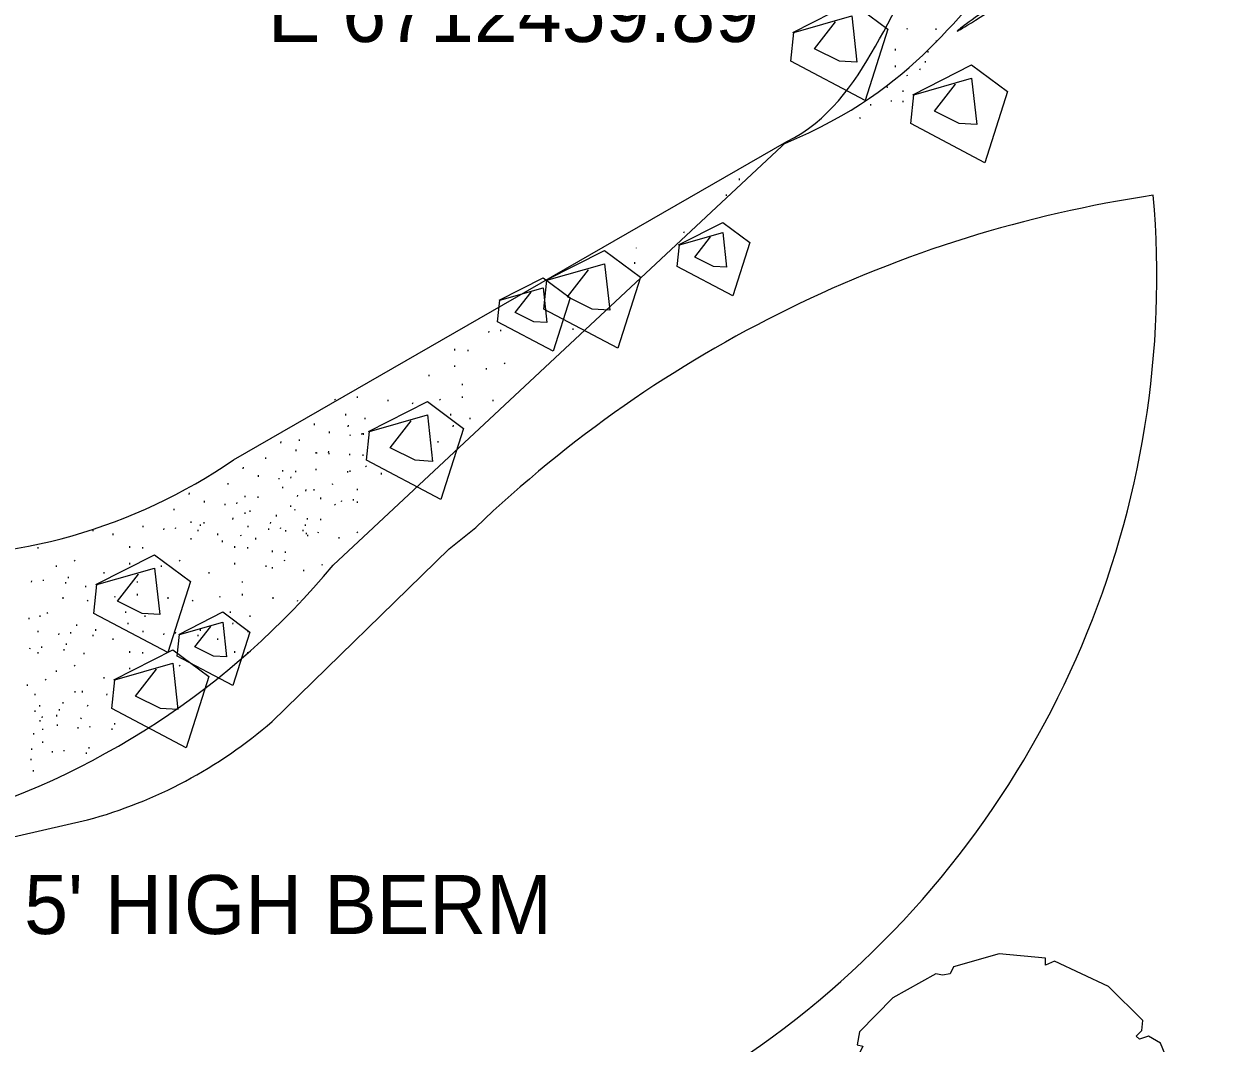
# Model space of a CAD drawing. Extents: x 6712138 to 6712574, y 1869536 to 1870160.
# Drawn here: x 6712397.9 to 6712471.1, y 1869628.8 to 1869691 of the extents above; entities that cross this region are included whole.
import ezdxf

# ---------------------------------------------------------------- set-up
doc = ezdxf.new("R2010")
doc.units = 0
for name, color, linetype in [('A-COLS', 7, 'Continuous'), ('A-FLOR-PATT', 7, 'Continuous'), ('A-WALL', 7, 'Continuous'), ('I-WALL', 7, 'Continuous'), ('L-SITE-PAVE', 7, 'Continuous'), ('L-tree', 7, 'Continuous'), ('P-SANR-FIXT', 7, 'Continuous')]:
    doc.layers.add(name, color=color, linetype=linetype)

# ---------------------------------------------------------------- blocks, each defined once
blk = doc.blocks.new('TREE 1')
at = {"layer": 'L-tree'}
for p, q in [((-0.0275, 0.572), (-0.1682, 0.5324)), ((0.1167, 0.5588), (-0.0275, 0.572)), ((0.1167, 0.5368), (0.1167, 0.5588)), ((-0.1682, 0.5324), (-0.1785, 0.5104)), ((0.1441, 0.55), (0.1167, 0.5368)), ((0.3123, 0.4708), (0.1441, 0.55)), ((-0.2231, 0.5104), (-0.357, 0.4356)), ((-0.2025, 0.506), (-0.2231, 0.5104)), ((-0.1785, 0.5104), (-0.2025, 0.506)), ((0.4187, 0.3652), (0.3123, 0.4708)), ((-0.357, 0.4356), (-0.4599, 0.33)), ((0.4153, 0.3344), (0.4187, 0.3652)), ((-0.4599, 0.33), (-0.4668, 0.2904)), ((0.3981, 0.3168), (0.4153, 0.3344)), ((0.4084, 0.308), (0.3981, 0.3168)), ((0.4359, 0.3168), (0.4084, 0.308)), ((0.4737, 0.2948), (0.4359, 0.3168)), ((-0.4599, 0.264), (-0.4908, 0.2596)), ((-0.4668, 0.2904), (-0.4496, 0.286)), ((-0.4496, 0.286), (-0.4599, 0.264)), ((0.5183, 0.1848), (0.4737, 0.2948)), ((-0.4908, 0.2596), (-0.5389, 0.2156)), ((-0.5389, 0.2156), (-0.5766, 0.0528)), ((0.5183, 0.1496), (0.5183, 0.1848)), ((0.5423, 0.1012), (0.5183, 0.1496)), ((0.5492, -0.0308), (0.5423, 0.1012)), ((-0.5766, 0.0528), (-0.5595, -0.1232)), ((-0.0034, 0.0176), (-0.0206, 0.0088)), ((-0.0206, 0.0088), (-0.0137, 0)), ((-0.0137, 0), (0, 0)), ((0, 0), (-0.0034, 0.0176)), ((0.5251, -0.1628), (0.5492, -0.0308)), ((-0.5595, -0.1232), (-0.5286, -0.1364)), ((-0.5286, -0.1364), (-0.5251, -0.1628)), ((-0.5251, -0.1628), (-0.5354, -0.176)), ((-0.5354, -0.176), (-0.4393, -0.3432)), ((0.4839, -0.1892), (0.5251, -0.1628)), ((0.4634, -0.2068), (0.4839, -0.1892)), ((0.4702, -0.2288), (0.4634, -0.2068)), ((0.4462, -0.3168), (0.4942, -0.2464)), ((0.4839, -0.2288), (0.4702, -0.2288)), ((0.4942, -0.2464), (0.4839, -0.2288)), ((0.381, -0.396), (0.4462, -0.3168)), ((-0.4393, -0.3432), (-0.3844, -0.4136)), ((0.2437, -0.4884), (0.381, -0.396)), ((-0.3844, -0.4136), (-0.2952, -0.4664)), ((-0.2952, -0.4664), (-0.2815, -0.4576)), ((-0.2815, -0.4576), (-0.2609, -0.4488)), ((-0.2609, -0.4488), (-0.2471, -0.4664)), ((-0.2471, -0.4664), (-0.1991, -0.506)), ((-0.1991, -0.506), (-0.1373, -0.5368)), ((0.175, -0.5236), (0.1785, -0.506)), ((0.1785, -0.506), (0.1922, -0.4884)), ((0.1922, -0.4884), (0.2265, -0.484)), ((0.2265, -0.484), (0.2437, -0.4884)), ((-0.1373, -0.5368), (-0.0172, -0.5544)), ((-0.0172, -0.5544), (0.0892, -0.5456)), ((0.0892, -0.5456), (0.175, -0.5236))]:
    blk.add_line(p, q, dxfattribs=at)

msp = doc.modelspace()

# ---------------------------------------------------------------- linework, layer by layer
at = {"layer": 'A-FLOR-PATT'}
for p, q in [((6712451.799, 1869690.684), (6712451.769, 1869690.747)), ((6712453.55, 1869690.662), (6712453.55, 1869690.749)), ((6712453.569, 1869689.927), (6712453.569, 1869690.014)), ((6712451.075, 1869689.408), (6712451.075, 1869689.502)), ((6712453.055, 1869689.295), (6712453.055, 1869689.378)), ((6712451.075, 1869688.39), (6712451.075, 1869688.484)), ((6712452.559, 1869688.237), (6712452.595, 1869688.31)), ((6712452.902, 1869688.67), (6712452.902, 1869688.756)), ((6712451.799, 1869687.843), (6712451.769, 1869687.906)), ((6712450.58, 1869687.138), (6712450.554, 1869687.202)), ((6712451.532, 1869686.888), (6712451.542, 1869686.965)), ((6712449.552, 1869686.045), (6712449.552, 1869686.139)), ((6712450.812, 1869686.292), (6712450.822, 1869686.366)), ((6712451.532, 1869686.264), (6712451.542, 1869686.341)), ((6712448.886, 1869685.253), (6712448.923, 1869685.326)), ((6712441.538, 1869681.503), (6712441.538, 1869681.587)), ((6712440.741, 1869680.533), (6712440.741, 1869680.62)), ((6712438.154, 1869678.283), (6712438.19, 1869678.356)), ((6712435.267, 1869677.336), (6712435.267, 1869677.355)), ((6712435.147, 1869676.393), (6712435.147, 1869676.487)), ((6712426.249, 1869672.2), (6712426.259, 1869672.274)), ((6712426.969, 1869672.274), (6712426.979, 1869672.35)), ((6712431.393, 1869672.357), (6712431.393, 1869672.45)), ((6712424.171, 1869671.103), (6712424.171, 1869671.197)), ((6712424.975, 1869671.063), (6712424.975, 1869671.147)), ((6712424.179, 1869670.094), (6712424.179, 1869670.18)), ((6712426.095, 1869669.94), (6712426.095, 1869670.027)), ((6712427.235, 1869670.29), (6712427.206, 1869670.354)), ((6712422.602, 1869669.534), (6712422.602, 1869669.62)), ((6712418.235, 1869668.98), (6712418.235, 1869668.981)), ((6712424.639, 1869668.98), (6712424.639, 1869669.054)), ((6712416.881, 1869668.063), (6712416.855, 1869668.127)), ((6712418.235, 1869668.2), (6712418.235, 1869668.287)), ((6712420.108, 1869667.997), (6712420.108, 1869668.09)), ((6712421.591, 1869667.843), (6712421.628, 1869667.917)), ((6712423.285, 1869668.063), (6712423.259, 1869668.127)), ((6712424.639, 1869668.2), (6712424.639, 1869668.287)), ((6712426.512, 1869667.997), (6712426.512, 1869668.09)), ((6712417.518, 1869667.137), (6712417.518, 1869667.223)), ((6712418.705, 1869666.897), (6712418.705, 1869666.98)), ((6712423.922, 1869667.137), (6712423.922, 1869667.223)), ((6712425.109, 1869666.897), (6712425.109, 1869666.98)), ((6712415.595, 1869666.545), (6712415.612, 1869666.638)), ((6712417.658, 1869666.44), (6712417.675, 1869666.534)), ((6712424.062, 1869666.44), (6712424.079, 1869666.534)), ((6712413.555, 1869665.446), (6712413.572, 1869665.54)), ((6712414.681, 1869665.585), (6712414.681, 1869665.672)), ((6712416.522, 1869666.058), (6712416.522, 1869666.152)), ((6712417.782, 1869665.901), (6712417.792, 1869665.975)), ((6712418.502, 1869665.975), (6712418.512, 1869666.052)), ((6712418.585, 1869665.954), (6712418.585, 1869666.047)), ((6712423.148, 1869665.48), (6712423.148, 1869665.567)), ((6712414.482, 1869664.96), (6712414.482, 1869665.053)), ((6712415.705, 1869664.805), (6712415.705, 1869664.898)), ((6712415.742, 1869664.803), (6712415.752, 1869664.877)), ((6712416.462, 1869664.877), (6712416.472, 1869664.953)), ((6712416.509, 1869664.765), (6712416.509, 1869664.849)), ((6712417.767, 1869664.7), (6712417.767, 1869664.794)), ((6712418.571, 1869664.66), (6712418.571, 1869664.744)), ((6712411.254, 1869663.877), (6712411.271, 1869663.971)), ((6712412.642, 1869664.486), (6712412.642, 1869664.573)), ((6712418.769, 1869663.992), (6712418.739, 1869664.055)), ((6712412.181, 1869663.391), (6712412.181, 1869663.484)), ((6712413.441, 1869663.234), (6712413.451, 1869663.308)), ((6712413.665, 1869663.706), (6712413.665, 1869663.8)), ((6712414.161, 1869663.308), (6712414.171, 1869663.384)), ((6712414.469, 1869663.666), (6712414.469, 1869663.75)), ((6712415.712, 1869663.795), (6712415.712, 1869663.881)), ((6712417.629, 1869663.641), (6712417.629, 1869663.729)), ((6712417.775, 1869663.69), (6712417.775, 1869663.777)), ((6712419.691, 1869663.537), (6712419.691, 1869663.624)), ((6712410.34, 1869662.917), (6712410.34, 1869663.004)), ((6712413.672, 1869662.697), (6712413.672, 1869662.783)), ((6712415.072, 1869662.517), (6712415.089, 1869662.611)), ((6712415.589, 1869662.543), (6712415.589, 1869662.63)), ((6712416.729, 1869662.893), (6712416.699, 1869662.957)), ((6712418.235, 1869662.577), (6712418.235, 1869662.65)), ((6712407.959, 1869662.308), (6712407.976, 1869662.402)), ((6712408.886, 1869661.822), (6712408.886, 1869661.915)), ((6712410.866, 1869661.739), (6712410.876, 1869661.815)), ((6712411.363, 1869662.137), (6712411.363, 1869662.231)), ((6712412.167, 1869662.097), (6712412.167, 1869662.181)), ((6712414.56, 1869662.195), (6712414.597, 1869662.268)), ((6712415.999, 1869662.031), (6712415.999, 1869662.125)), ((6712417.259, 1869661.874), (6712417.269, 1869661.948)), ((6712417.979, 1869661.948), (6712417.989, 1869662.025)), ((6712418.235, 1869661.797), (6712418.235, 1869661.884)), ((6712407.045, 1869661.348), (6712407.045, 1869661.435)), ((6712410.146, 1869661.665), (6712410.156, 1869661.739)), ((6712411.371, 1869661.128), (6712411.371, 1869661.214)), ((6712411.673, 1869661.248), (6712411.673, 1869661.331)), ((6712413.287, 1869660.974), (6712413.287, 1869661.061)), ((6712414.158, 1869661.557), (6712414.158, 1869661.645)), ((6712414.427, 1869661.324), (6712414.398, 1869661.388)), ((6712416.881, 1869661.66), (6712416.855, 1869661.724)), ((6712405.149, 1869660.305), (6712405.149, 1869660.399)), ((6712408.068, 1869660.568), (6712408.068, 1869660.662)), ((6712408.653, 1869660.399), (6712408.653, 1869660.482)), ((6712408.872, 1869660.528), (6712408.872, 1869660.612)), ((6712410.626, 1869660.791), (6712410.643, 1869660.885)), ((6712411.553, 1869660.305), (6712411.553, 1869660.399)), ((6712412.928, 1869660.53), (6712412.944, 1869660.623)), ((6712415.057, 1869660.399), (6712415.057, 1869660.482)), ((6712415.182, 1869660.777), (6712415.182, 1869660.871)), ((6712415.986, 1869660.737), (6712415.986, 1869660.821)), ((6712402.095, 1869660.059), (6712402.095, 1869660.145)), ((6712403.309, 1869659.831), (6712403.309, 1869659.919)), ((6712406.409, 1869660.148), (6712406.419, 1869660.222)), ((6712407.129, 1869660.222), (6712407.139, 1869660.299)), ((6712408.076, 1869659.559), (6712408.076, 1869659.645)), ((6712408.499, 1869660.059), (6712408.499, 1869660.145)), ((6712409.713, 1869659.831), (6712409.713, 1869659.919)), ((6712411.132, 1869659.755), (6712411.103, 1869659.819)), ((6712412.014, 1869659.57), (6712412.014, 1869659.657)), ((6712412.813, 1869660.148), (6712412.823, 1869660.222)), ((6712413.533, 1869660.222), (6712413.543, 1869660.299)), ((6712413.855, 1869660.043), (6712413.855, 1869660.137)), ((6712414.903, 1869660.059), (6712414.903, 1869660.145)), ((6712415.115, 1869659.887), (6712415.124, 1869659.96)), ((6712415.189, 1869659.768), (6712415.189, 1869659.854)), ((6712415.835, 1869659.96), (6712415.844, 1869660.037)), ((6712417.106, 1869659.614), (6712417.106, 1869659.701)), ((6712418.246, 1869659.965), (6712418.216, 1869660.028)), ((6712398.732, 1869659.011), (6712398.732, 1869659.095)), ((6712404.332, 1869659.051), (6712404.332, 1869659.145)), ((6712405.136, 1869659.011), (6712405.136, 1869659.095)), ((6712409.992, 1869659.405), (6712409.992, 1869659.492)), ((6712410.736, 1869659.051), (6712410.736, 1869659.145)), ((6712411.54, 1869659.011), (6712411.54, 1869659.095)), ((6712413.037, 1869658.79), (6712413.037, 1869658.883)), ((6712400.992, 1869658.239), (6712400.962, 1869658.302)), ((6712404.339, 1869658.042), (6712404.339, 1869658.128)), ((6712407.396, 1869658.239), (6712407.366, 1869658.302)), ((6712410.743, 1869658.042), (6712410.743, 1869658.128)), ((6712413.8, 1869658.239), (6712413.77, 1869658.302)), ((6712413.841, 1869658.75), (6712413.841, 1869658.834)), ((6712399.852, 1869657.888), (6712399.852, 1869657.975)), ((6712402.762, 1869657.482), (6712402.762, 1869657.568)), ((6712406.256, 1869657.888), (6712406.256, 1869657.975)), ((6712409.166, 1869657.482), (6712409.166, 1869657.568)), ((6712412.66, 1869657.888), (6712412.66, 1869657.975)), ((6712413.044, 1869657.78), (6712413.044, 1869657.867)), ((6712414.961, 1869657.627), (6712414.961, 1869657.714)), ((6712416.101, 1869657.977), (6712416.072, 1869658.04)), ((6712398.338, 1869656.958), (6712398.347, 1869657.031)), ((6712399.058, 1869657.031), (6712399.067, 1869657.108)), ((6712400.427, 1869656.868), (6712400.427, 1869656.955)), ((6712400.581, 1869657.208), (6712400.581, 1869657.291)), ((6712401.641, 1869656.641), (6712401.641, 1869656.728)), ((6712404.799, 1869656.928), (6712404.799, 1869657.002)), ((6712411.203, 1869656.928), (6712411.203, 1869657.002)), ((6712400.269, 1869655.945), (6712400.269, 1869656.039)), ((6712403.445, 1869656.011), (6712403.419, 1869656.075)), ((6712404.799, 1869656.148), (6712404.799, 1869656.235)), ((6712406.673, 1869655.945), (6712406.673, 1869656.039)), ((6712409.849, 1869656.011), (6712409.823, 1869656.075)), ((6712411.203, 1869656.148), (6712411.203, 1869656.235)), ((6712413.077, 1869655.945), (6712413.077, 1869656.039)), ((6712401.752, 1869655.791), (6712401.789, 1869655.865)), ((6712408.156, 1869655.791), (6712408.193, 1869655.865)), ((6712414.56, 1869655.791), (6712414.597, 1869655.865)), ((6712398.184, 1869654.698), (6712398.184, 1869654.785)), ((6712398.865, 1869654.845), (6712398.865, 1869654.928)), ((6712399.324, 1869655.048), (6712399.295, 1869655.111)), ((6712404.082, 1869655.085), (6712404.082, 1869655.171)), ((6712404.222, 1869654.388), (6712404.239, 1869654.482)), ((6712405.269, 1869654.845), (6712405.269, 1869654.928)), ((6712410.486, 1869655.085), (6712410.486, 1869655.171)), ((6712410.626, 1869654.388), (6712410.643, 1869654.482)), ((6712411.673, 1869654.845), (6712411.673, 1869654.928)), ((6712398.745, 1869653.902), (6712398.745, 1869653.995)), ((6712400.005, 1869653.745), (6712400.015, 1869653.819)), ((6712400.725, 1869653.819), (6712400.735, 1869653.895)), ((6712401.095, 1869654.291), (6712401.095, 1869654.378)), ((6712402.095, 1869653.655), (6712402.095, 1869653.742)), ((6712402.249, 1869653.995), (6712402.249, 1869654.079)), ((6712405.149, 1869653.902), (6712405.149, 1869653.995)), ((6712406.409, 1869653.745), (6712406.419, 1869653.819)), ((6712407.129, 1869653.819), (6712407.139, 1869653.895)), ((6712408.499, 1869653.655), (6712408.499, 1869653.742)), ((6712408.653, 1869653.995), (6712408.653, 1869654.079)), ((6712411.553, 1869653.902), (6712411.553, 1869653.995)), ((6712398.953, 1869652.952), (6712398.963, 1869653.029)), ((6712400.476, 1869653.129), (6712400.476, 1869653.212)), ((6712403.309, 1869653.428), (6712403.309, 1869653.515)), ((6712409.713, 1869653.428), (6712409.713, 1869653.515)), ((6712398.233, 1869652.878), (6712398.243, 1869652.952)), ((6712398.732, 1869652.608), (6712398.732, 1869652.692)), ((6712400.323, 1869652.789), (6712400.323, 1869652.875)), ((6712401.536, 1869652.561), (6712401.536, 1869652.649)), ((6712404.332, 1869652.648), (6712404.332, 1869652.742)), ((6712405.136, 1869652.608), (6712405.136, 1869652.692)), ((6712410.736, 1869652.648), (6712410.736, 1869652.742)), ((6712411.54, 1869652.608), (6712411.54, 1869652.692)), ((6712399.852, 1869651.485), (6712399.852, 1869651.572)), ((6712400.992, 1869651.835), (6712400.962, 1869651.899)), ((6712404.339, 1869651.639), (6712404.339, 1869651.725)), ((6712407.396, 1869651.835), (6712407.366, 1869651.899)), ((6712399.22, 1869650.969), (6712399.19, 1869651.032)), ((6712402.762, 1869651.079), (6712402.762, 1869651.165)), ((6712398.08, 1869650.618), (6712398.08, 1869650.705)), ((6712398.555, 1869650.055), (6712398.555, 1869650.149)), ((6712400.99, 1869650.212), (6712400.99, 1869650.298)), ((6712401.438, 1869650.222), (6712401.438, 1869650.315)), ((6712402.921, 1869650.068), (6712402.958, 1869650.142)), ((6712398.847, 1869649.362), (6712398.847, 1869649.448)), ((6712400.269, 1869649.542), (6712400.269, 1869649.635)), ((6712401.752, 1869649.388), (6712401.789, 1869649.462)), ((6712398.563, 1869649.046), (6712398.563, 1869649.132)), ((6712398.987, 1869648.665), (6712399.004, 1869648.758)), ((6712399.869, 1869648.757), (6712399.869, 1869648.851)), ((6712400.034, 1869649.122), (6712400.034, 1869649.205)), ((6712401.352, 1869648.604), (6712401.389, 1869648.677)), ((6712398.865, 1869648.442), (6712398.865, 1869648.525)), ((6712399.023, 1869647.932), (6712399.023, 1869648.006)), ((6712399.914, 1869648.178), (6712399.914, 1869648.272)), ((6712401.174, 1869648.022), (6712401.184, 1869648.095)), ((6712401.894, 1869648.095), (6712401.904, 1869648.172)), ((6712403.264, 1869647.932), (6712403.264, 1869648.018)), ((6712403.418, 1869648.272), (6712403.418, 1869648.355)), ((6712398.465, 1869647.657), (6712398.465, 1869647.74)), ((6712399.023, 1869647.152), (6712399.023, 1869647.239)), ((6712398.345, 1869646.714), (6712398.345, 1869646.808)), ((6712399.605, 1869646.557), (6712399.615, 1869646.631)), ((6712400.325, 1869646.631), (6712400.335, 1869646.708)), ((6712401.695, 1869646.468), (6712401.695, 1869646.554)), ((6712401.849, 1869646.808), (6712401.849, 1869646.891)), ((6712398.306, 1869646.089), (6712398.306, 1869646.175)), ((6712398.446, 1869645.392), (6712398.463, 1869645.486))]:
    msp.add_line(p, q, dxfattribs=at)
at = {"layer": 'A-WALL'}
for p, q in [((6712410.662, 1869664.431), (6712444.439, 1869683.86)), ((6712416.747, 1869657.995), (6712444.439, 1869683.86)), ((6712413.026, 1869648.458), (6712423.83, 1869658.994)), ((6712341.53, 1869628.825), (6712401.744, 1869642.44))]:
    msp.add_line(p, q, dxfattribs=at)
for centre, radius, start, end in [((6712409.461, 1869675.569), 57.555, 252.99796, 4.98497), ((6712477.962, 1869605.494), 75.901, 98.45751, 133.78207), ((6712391.588, 1869692.154), 33.651, 267.25855, 304.52858), ((6712385.442, 1869708.358), 62.533, 307.87024, 309.76908), ((6712379.319, 1869689.117), 48.676, 286.08812, 320.25604), ((6712394.208, 1869670.15), 28.717, 285.21384, 310.94114)]:
    msp.add_arc(centre, radius, start, end, dxfattribs=at)
at = {"layer": 'L-SITE-PAVE'}
for points in [[(6712444.439, 1869683.86), (6712449.499, 1869686.363), (6712451.519, 1869698.635), (6712471.056, 1869706.558), (6712444.439, 1869683.86), (6712471.056, 1869706.558)], [(6712444.301, 1869683.731), (6712452.504, 1869687.124), (6712457.335, 1869696.824), (6712471.056, 1869700.971), (6712444.301, 1869683.731), (6712471.056, 1869700.971)]]:
    msp.add_open_spline(points, degree=3, dxfattribs=at)
at = {"layer": 'P-SANR-FIXT'}
for points in [[(6712444.808, 1869690.517), (6712448.394, 1869692.341), (6712450.597, 1869690.706), (6712449.212, 1869686.366), (6712444.681, 1869688.756), (6712444.87, 1869690.517), (6712448.394, 1869691.523), (6712448.709, 1869688.693), (6712447.639, 1869688.756), (6712446.129, 1869689.511), (6712447.413, 1869691.161), (6712447.413, 1869691.161)], [(6712452.119, 1869686.711), (6712455.706, 1869688.535), (6712457.909, 1869686.9), (6712456.524, 1869682.56), (6712451.993, 1869684.95), (6712452.182, 1869686.711), (6712455.706, 1869687.717), (6712456.021, 1869684.887), (6712454.95, 1869684.95), (6712453.44, 1869685.705), (6712454.724, 1869687.355), (6712454.724, 1869687.355)], [(6712437.828, 1869677.543), (6712440.518, 1869678.911), (6712442.17, 1869677.685), (6712441.132, 1869674.43), (6712437.733, 1869676.222), (6712437.875, 1869677.543), (6712440.518, 1869678.298), (6712440.754, 1869676.175), (6712439.951, 1869676.222), (6712438.819, 1869676.788), (6712439.782, 1869678.026), (6712439.782, 1869678.026)], [(6712429.719, 1869675.387), (6712433.305, 1869677.211), (6712435.508, 1869675.575), (6712434.123, 1869671.236), (6712429.593, 1869673.626), (6712429.781, 1869675.387), (6712433.305, 1869676.393), (6712433.62, 1869673.563), (6712432.55, 1869673.626), (6712431.04, 1869674.38), (6712432.324, 1869676.031), (6712432.324, 1869676.031)], [(6712426.866, 1869674.17), (6712429.557, 1869675.538), (6712431.209, 1869674.311), (6712430.17, 1869671.057), (6712426.772, 1869672.849), (6712426.913, 1869674.17), (6712429.557, 1869674.925), (6712429.793, 1869672.802), (6712428.99, 1869672.849), (6712427.857, 1869673.415), (6712428.82, 1869674.653), (6712428.82, 1869674.653)], [(6712418.907, 1869666.155), (6712422.494, 1869667.979), (6712424.697, 1869666.344), (6712423.312, 1869662.004), (6712418.781, 1869664.394), (6712418.97, 1869666.155), (6712422.494, 1869667.161), (6712422.809, 1869664.331), (6712421.739, 1869664.394), (6712420.229, 1869665.149), (6712421.512, 1869666.799), (6712421.512, 1869666.799)], [(6712402.256, 1869656.807), (6712405.843, 1869658.631), (6712408.046, 1869656.996), (6712406.661, 1869652.656), (6712402.13, 1869655.046), (6712402.319, 1869656.807), (6712405.843, 1869657.813), (6712406.158, 1869654.983), (6712405.088, 1869655.046), (6712403.578, 1869655.801), (6712404.862, 1869657.451), (6712404.862, 1869657.451)], [(6712407.316, 1869653.769), (6712410.006, 1869655.137), (6712411.658, 1869653.91), (6712410.619, 1869650.655), (6712407.221, 1869652.448), (6712407.363, 1869653.769), (6712410.006, 1869654.523), (6712410.242, 1869652.401), (6712409.439, 1869652.448), (6712408.307, 1869653.014), (6712409.269, 1869654.252), (6712409.269, 1869654.252)], [(6712403.363, 1869651.001), (6712406.95, 1869652.825), (6712409.153, 1869651.19), (6712407.768, 1869646.85), (6712403.237, 1869649.24), (6712403.426, 1869651.001), (6712406.95, 1869652.007), (6712407.265, 1869649.177), (6712406.195, 1869649.24), (6712404.685, 1869649.995), (6712405.969, 1869651.645), (6712405.969, 1869651.645)]]:
    msp.add_lwpolyline(points, dxfattribs=at)

# ---------------------------------------------------------------- block references
at = {"layer": 'L-tree', "xscale": 19.685038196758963, "yscale": 19.685039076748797}
msp.add_blockref('TREE 1', (6712457.925, 1869623.004), dxfattribs=at)

# ---------------------------------------------------------------- texts
at = {"layer": 'A-COLS'}
msp.add_text("5' HIGH BERM", height=3.6, dxfattribs=at).set_placement((6712397.883, 1869635.478))
at = {"layer": 'I-WALL'}
msp.add_text('E 6712459.89', height=3.6, dxfattribs=at).set_placement((6712412.753, 1869689.928))

doc.saveas('drawing.dxf')
